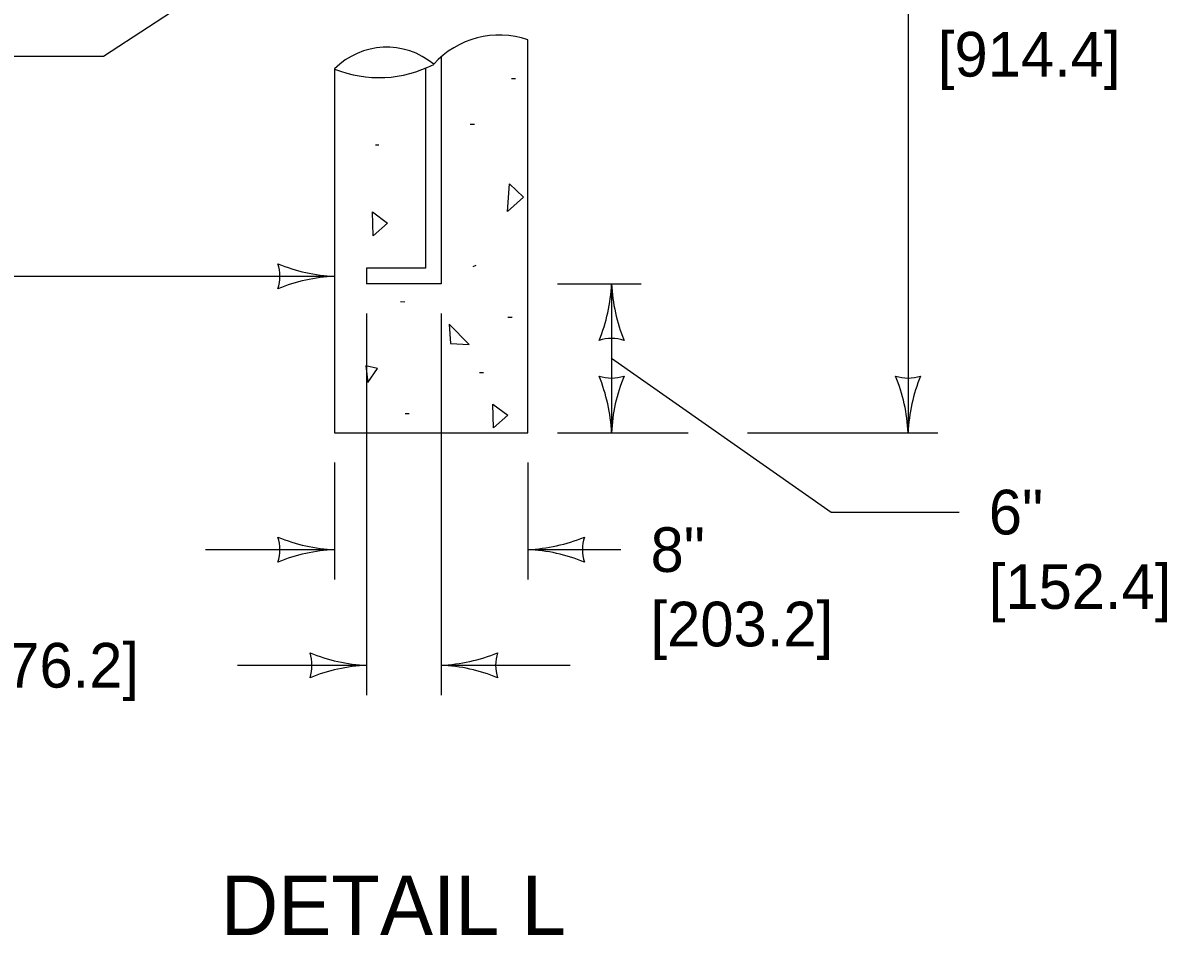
# Model space of a CAD drawing. Extents: x 49991.4 to 50021, y 49987.6 to 50011.4.
# Drawn here: x 50006.305 to 50007.843, y 49991.807 to 49993.032 of the extents above; entities that cross this region are included whole.
import ezdxf

# ---------------------------------------------------------------- set-up
doc = ezdxf.new("R2010")
doc.units = 0
for name, color, linetype in [('Level 1', 7, 'Continuous'), ('Level 2', 7, 'Continuous'), ('Level 3', 7, 'Continuous')]:
    doc.layers.add(name, color=color, linetype=linetype)

msp = doc.modelspace()

# ---------------------------------------------------------------- linework, layer by layer
at = {"layer": 'Level 1'}
for p, q in [((50006.9833, 49992.4817), (50006.9833, 49993.0097)), ((50006.8667, 49992.9863), (50006.8667, 49992.6817)), ((50006.7236, 49992.9704), (50006.7236, 49992.4817)), ((50006.8459, 49992.9715), (50006.8459, 49992.7028)), ((50006.9612, 49992.9574), (50006.9667, 49992.9574)), ((50006.906, 49992.8961), (50006.9117, 49992.8961)), ((50006.7786, 49992.8683), (50006.783, 49992.8683)), ((50006.7667, 49992.7028), (50006.7667, 49992.6817)), ((50006.8459, 49992.7028), (50006.7667, 49992.7028)), ((50006.91, 49992.705), (50006.914, 49992.7068)), ((50006.8667, 49992.6817), (50006.7667, 49992.6817)), ((50006.8124, 49992.6581), (50006.8182, 49992.6574)), ((50006.9564, 49992.6371), (50006.9622, 49992.6371)), ((50006.9186, 49992.5628), (50006.9236, 49992.5628)), ((50006.7674, 49992.54), (50006.7674, 49992.54)), ((50006.8185, 49992.5073), (50006.824, 49992.5073)), ((50006.7236, 49992.4817), (50006.9833, 49992.4817))]:
    msp.add_line(p, q, dxfattribs=at)
for points in [[(50006.9586, 49992.8161), (50006.9774, 49992.7981), (50006.9562, 49992.779)], [(50006.7746, 49992.7784), (50006.7947, 49992.7634), (50006.7756, 49992.7464)], [(50006.8794, 49992.6014), (50006.9046, 49992.6003), (50006.8777, 49992.6276)], [(50006.7656, 49992.5714), (50006.7685, 49992.549), (50006.7813, 49992.568)], [(50006.9363, 49992.5202), (50006.9564, 49992.5052), (50006.9373, 49992.4882)]]:
    msp.add_lwpolyline(points, close=True, dxfattribs=at)
for centre, radius, start, end in [((50006.9451, 49992.8973), 0.1187, 71.2362, 138.0102), ((50006.7937, 49992.9012), 0.0985, 50.0466, 135.3652), ((50006.7834, 49993.1192), 0.1604, 248.1246, 297.2871)]:
    msp.add_arc(centre, radius, start, end, dxfattribs=at)
at = {"layer": 'Level 3'}
for p, q in [((50007.4945, 49993.5987), (50007.4945, 49992.4817)), ((50006.4129, 49992.9875), (50006.8459, 49993.2701)), ((50006.1249, 49992.9875), (50006.4129, 49992.9875)), ((50005.9149, 49992.6919), (50006.7236, 49992.6919)), ((50007.0233, 49992.6817), (50007.1359, 49992.6817)), ((50007.0959, 49992.6817), (50007.0959, 49992.4817)), ((50006.7667, 49992.6417), (50006.7667, 49992.1292)), ((50006.8667, 49992.6417), (50006.8667, 49992.1292)), ((50007.0233, 49992.4817), (50007.1988, 49992.4817)), ((50007.2788, 49992.4817), (50007.5345, 49992.4817)), ((50006.7236, 49992.4417), (50006.7236, 49992.2846)), ((50006.9833, 49992.4417), (50006.9833, 49992.2846)), ((50006.5502, 49992.3246), (50006.7236, 49992.3246)), ((50006.9833, 49992.3246), (50007.1083, 49992.3246)), ((50006.5933, 49992.1692), (50006.7667, 49992.1692)), ((50006.8667, 49992.1692), (50007.0401, 49992.1692))]:
    msp.add_line(p, q, dxfattribs=at)
msp.add_lwpolyline([(50007.0959, 49992.5817), (50007.3912, 49992.375), (50007.5629, 49992.375)], dxfattribs=at)
for centre, radius, start, end in [((50006.7328, 49992.914), 0.2223, 247.456, 267.6395), ((50006.5954, 49992.6919), 0.0548, 342.1388, 17.8612), ((50006.7351, 49992.4592), 0.233, 92.8273, 112.0772), ((50006.8738, 49992.6909), 0.2223, 337.456, 357.6395), ((50007.3286, 49992.6932), 0.233, 182.8273, 202.0772), ((50007.0959, 49992.5535), 0.0548, 72.1388, 107.8612), ((50007.0959, 49992.6099), 0.0548, 252.1388, 287.8612), ((50006.8632, 49992.4702), 0.233, 2.8273, 22.0772), ((50007.318, 49992.4725), 0.2223, 157.456, 177.6395), ((50007.4945, 49992.6099), 0.0548, 252.1388, 287.8612), ((50007.2618, 49992.4702), 0.233, 2.8273, 22.0772), ((50007.7166, 49992.4725), 0.2223, 157.456, 177.6395), ((50006.7328, 49992.5467), 0.2223, 247.456, 267.6395), ((50006.5954, 49992.3246), 0.0548, 342.1388, 17.8612), ((50006.9718, 49992.5573), 0.233, 272.8273, 292.0772), ((50007.1115, 49992.3246), 0.0548, 162.1388, 197.8612), ((50006.7351, 49992.0919), 0.233, 92.8273, 112.0772), ((50006.9741, 49992.1025), 0.2223, 67.456, 87.6395), ((50006.7759, 49992.3913), 0.2223, 247.456, 267.6395), ((50006.6385, 49992.1692), 0.0548, 342.1388, 17.8612), ((50006.8552, 49992.4019), 0.233, 272.8273, 292.0772), ((50006.9949, 49992.1692), 0.0548, 162.1388, 197.8612), ((50006.7782, 49991.9365), 0.233, 92.8273, 112.0772), ((50006.8575, 49991.9471), 0.2223, 67.456, 87.6395)]:
    msp.add_arc(centre, radius, start, end, dxfattribs=at)

# ---------------------------------------------------------------- texts
at = {"layer": 'Level 2'}
for s, height, p in [('[914.4]', 0.06, (50007.5345, 49992.9602)), ('6"', 0.06, (50007.6029, 49992.345)), ('8"', 0.06, (50007.1483, 49992.2946)), ('[152.4]', 0.06, (50007.6029, 49992.245)), ('[203.2]', 0.06, (50007.1483, 49992.1946)), ('3" [76.2]', 0.06, (50006.1647, 49992.1392)), ('DETAIL L', 0.08, (50006.5707, 49991.8067))]:
    msp.add_text(s, height=height, dxfattribs=at).set_placement(p)

doc.saveas('drawing.dxf')
